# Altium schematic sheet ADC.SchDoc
size A4
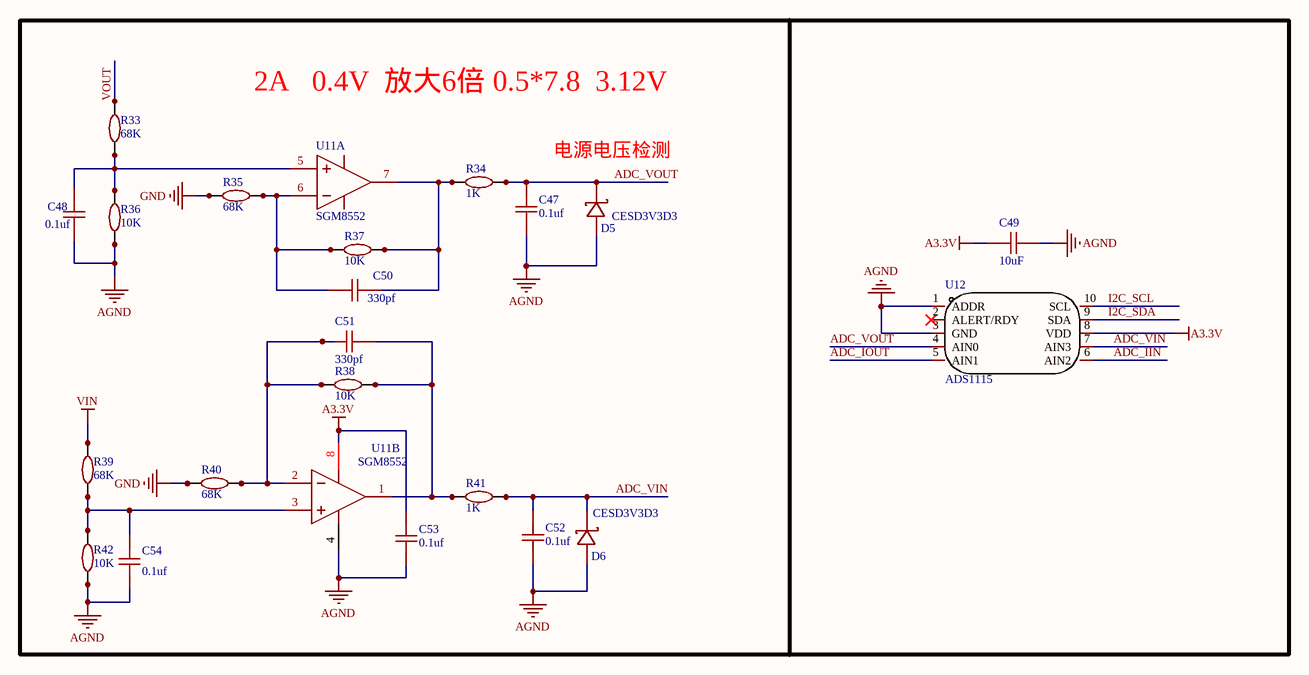
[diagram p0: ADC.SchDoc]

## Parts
C47  0.1uf  [C0402]
C48  0.1uf  [C0402]
C49  10uF  [C0402]
C50  330pf  [C0402]
C51  330pf  [C0402]
C52  0.1uf  [C0402]
C53  0.1uf  [C0402]
C54  0.1uf  [C0402]
D5  CESD3V3D3  [SOD-323]
D6  CESD3V3D3  [SOD-323]
R33  68K  [R0402]
R34  1K  [R0402]
R35  68K  [R0402]
R36  10K  [R0402]
R37  10K  [R0402]
R38  10K  [R0402]
R39  68K  [R0402]
R40  68K  [R0402]
R41  1K  [R0402]
R42  10K  [R0402]
U11  SGM8552  [SOP-8]  (parts A,B of 2)
U12  ADS1115  [MSOP-10]

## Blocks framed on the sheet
2A   0.4V  放大6倍 0.5*7.8  3.12V: C47 C48 C50-C54 D5 D6 R33-R42 U11

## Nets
A3.3V: C49.1 C53.1 U11.8(+VS) U12.8(VDD)
AGND: C47.1 C48.1 C49.2 C52.2 C53.2 C54.1 D5.2 D6.2 R36.1 R42.1 U11.4(-VS) U12.1(ADDR) U12.3(GND)
GND: R35.2 R40.2
VIN: R39.2
ADC_IIN: U12.6(AIN2)
ADC_IOUT: U12.5(AIN1)
ADC_VIN: C52.1 D6.1 R41.1 U12.7(AIN3)
ADC_VOUT: C47.2 D5.1 R34.1 U12.4(AIN0)
I2C_SCL: U12.10(SCL)
I2C_SDA: U12.9(SDA)
VOUT: R33.2
NetC48_2: C48.2 R33.1 R36.2 U11.5(INB+)
NetC50_1: C50.1 R34.2 R37.2 U11.7(OUTB)
NetC50_2: C50.2 R35.1 R37.1 U11.6(INB-)
NetC51_1: C51.1 R38.1 R41.2 U11.1(OUTA)
NetC51_2: C51.2 R38.2 R40.1 U11.2(INA-)
NetC54_2: C54.2 R39.1 R42.2 U11.3(INA+)

Not connected (* = marked no-connect by the designer): U12 2(ALERT/RDY)*

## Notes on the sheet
- 电源电压检测

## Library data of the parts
C47-C54 = 贴片电容
D5 D6 = SK-33
R33-R42 = 贴片电阻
